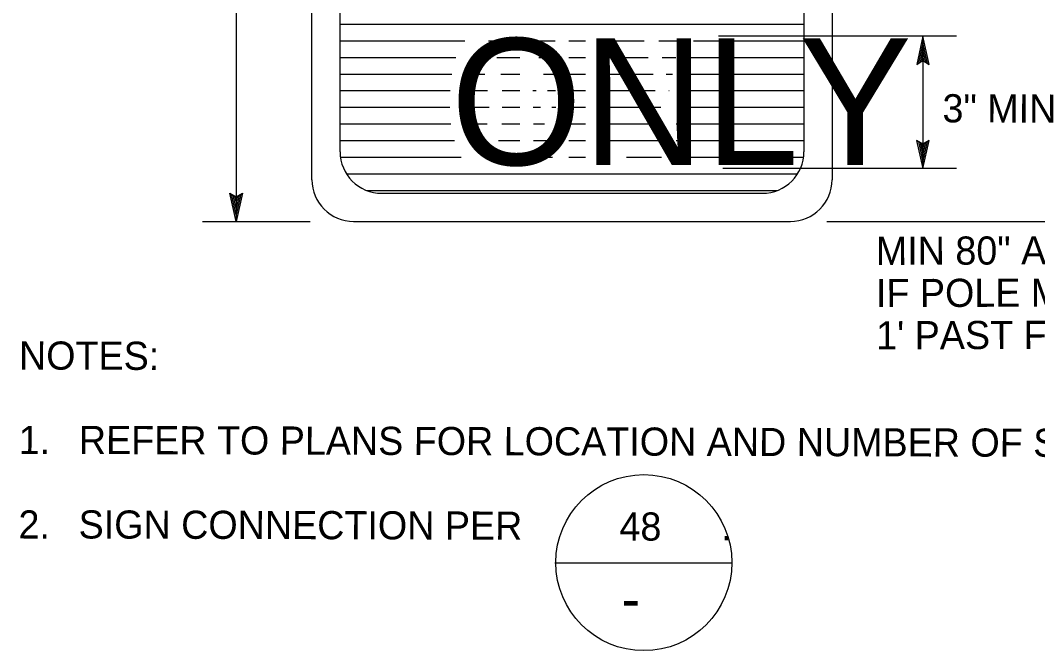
# Model space of a CAD drawing. Extents: x -121933 to -117742, y -103160 to -100084.
# Drawn here: x -118311.6 to -118094.9, y -101568.6 to -101434.3 of the extents above; entities that cross this region are included whole.
import ezdxf

# ---------------------------------------------------------------- set-up
doc = ezdxf.new("R2010")
doc.units = 0
for name, color, linetype in [('57 Undefined', 7, 'Continuous'), ('60 Nongeo Data', 7, 'Continuous'), ('Control (1)', 7, 'Continuous'), ('G-MARK', 7, 'Continuous'), ('G-TEXT', 7, 'Continuous'), ('Misc CnstDet(22)', 7, 'Continuous'), ('Sheet Format(10)', 7, 'Continuous')]:
    doc.layers.add(name, color=color, linetype=linetype)

msp = doc.modelspace()

# ---------------------------------------------------------------- linework, layer by layer
at = {"layer": '60 Nongeo Data'}
for p, q in [((-118249.47, -101468.31), (-118249.47, -101320.9)), ((-118138.69, -101320.93), (-118138.69, -101468.28)), ((-118243.48, -101462.3), (-118243.48, -101326.92)), ((-118144.67, -101326.92), (-118144.67, -101462.3)), ((-118243.48, -101435.11), (-118144.67, -101435.11)), ((-118243.48, -101438.66), (-118216.9, -101438.66)), ((-118211.87, -101438.66), (-118205.17, -101438.66)), ((-118202.1, -101438.66), (-118197.66, -101438.66)), ((-118194.78, -101438.66), (-118191.18, -101438.66)), ((-118187.97, -101438.66), (-118178.68, -101438.66)), ((-118175.58, -101438.66), (-118171.17, -101438.66)), ((-118168.18, -101438.66), (-118144.67, -101438.66)), ((-118243.48, -101442.2), (-118218.85, -101442.2)), ((-118214.99, -101442.2), (-118213.78, -101442.2)), ((-118210.12, -101442.2), (-118205.17, -101442.2)), ((-118201.15, -101442.2), (-118197.6, -101442.2)), ((-118194.78, -101442.2), (-118191.18, -101442.2)), ((-118187.97, -101442.2), (-118177.89, -101442.2)), ((-118174.85, -101442.2), (-118171.95, -101442.2)), ((-118169.01, -101442.2), (-118144.67, -101442.2)), ((-118243.48, -101445.75), (-118219.67, -101445.75)), ((-118216.75, -101445.75), (-118212.66, -101445.75)), ((-118209.26, -101445.75), (-118205.17, -101445.75)), ((-118200.13, -101445.75), (-118197.66, -101445.75)), ((-118194.78, -101445.75), (-118191.18, -101445.75)), ((-118187.97, -101445.75), (-118176.82, -101445.75)), ((-118174, -101445.75), (-118172.71, -101445.75)), ((-118169.9, -101445.75), (-118144.67, -101445.75)), ((-118243.48, -101449.3), (-118220.02, -101449.3)), ((-118217.14, -101449.3), (-118212.09, -101449.3)), ((-118208.98, -101449.3), (-118205.17, -101449.3)), ((-118202.44, -101449.3), (-118201.71, -101449.3)), ((-118199.28, -101449.3), (-118197.6, -101449.3)), ((-118194.78, -101449.3), (-118191.18, -101449.3)), ((-118187.97, -101449.3), (-118176.37, -101449.3)), ((-118173.44, -101449.3), (-118173.35, -101449.3)), ((-118170.74, -101449.3), (-118144.67, -101449.3)), ((-118243.48, -101452.84), (-118220.1, -101452.84)), ((-118217.18, -101452.84), (-118211.76, -101452.84)), ((-118208.95, -101452.84), (-118205.17, -101452.84)), ((-118202.33, -101452.84), (-118200.81, -101452.84)), ((-118198.35, -101452.84), (-118197.54, -101452.84)), ((-118194.78, -101452.84), (-118191.18, -101452.84)), ((-118187.97, -101452.84), (-118175.18, -101452.84)), ((-118171.69, -101452.84), (-118144.67, -101452.84)), ((-118243.48, -101456.39), (-118219.87, -101456.39)), ((-118216.79, -101456.39), (-118212.15, -101456.39)), ((-118209.03, -101456.39), (-118205.17, -101456.39)), ((-118202.27, -101456.39), (-118199.96, -101456.39)), ((-118197.51, -101456.39), (-118197.37, -101456.39)), ((-118194.78, -101456.39), (-118191.18, -101456.39)), ((-118187.97, -101456.39), (-118174.85, -101456.39)), ((-118171.86, -101456.39), (-118144.67, -101456.39)), ((-118243.48, -101459.94), (-118219.13, -101459.94)), ((-118215.5, -101459.94), (-118213.36, -101459.94)), ((-118209.77, -101459.94), (-118205.17, -101459.94)), ((-118202.27, -101459.94), (-118198.89, -101459.94)), ((-118194.78, -101459.94), (-118191.18, -101459.94)), ((-118187.97, -101459.94), (-118175.13, -101459.94)), ((-118171.86, -101459.94), (-118144.67, -101459.94)), ((-118243.4, -101463.49), (-118217.72, -101463.49)), ((-118211.21, -101463.49), (-118205.17, -101463.49)), ((-118202.22, -101463.49), (-118198.22, -101463.49)), ((-118194.78, -101463.49), (-118191.18, -101463.49)), ((-118182.45, -101463.49), (-118175.01, -101463.49)), ((-118171.86, -101463.49), (-118144.75, -101463.49)), ((-118242.11, -101467.03), (-118146.04, -101467.03)), ((-118237.78, -101470.58), (-118150.37, -101470.58)), ((-118234.61, -101471.16), (-118153.54, -101471.16)), ((-118245.63, -101475.59), (-118245.63, -101475.59)), ((-118244.6, -101476.2), (-118244.6, -101476.2)), ((-118240.63, -101477.15), (-118147.52, -101477.15))]:
    msp.add_line(p, q, dxfattribs=at)
for centre, start, end in [((-118234.61, -101462.3), 180, 270), ((-118153.54, -101462.3), 270, 0), ((-118240.6, -101468.28), 180, 270), ((-118147.56, -101468.28), 270, 0)]:
    msp.add_arc(centre, 8.87, start, end, dxfattribs=at)
at = {"layer": 'Control (1)'}
msp.add_line((-118197.73, -101549.92), (-118160.03, -101549.92), dxfattribs=at)
msp.add_circle((-118178.78, -101549.87), 18.75, dxfattribs=at)
at = {"layer": 'G-MARK'}
for p, q in [((-118265.63, -101312.06), (-118265.63, -101477.15)), ((-118119.33, -101437.7), (-118119.33, -101465.9))]:
    msp.add_line(p, q, dxfattribs=at)
at = {"layer": 'G-TEXT'}
for p, q in [((-118119.33, -101437.7), (-118120.66, -101443.7)), ((-118117.99, -101443.7), (-118119.33, -101437.7)), ((-118119.33, -101437.7), (-118119.33, -101437.7)), ((-118119.33, -101439.09), (-118120.3, -101443.47)), ((-118119.33, -101440.46), (-118119.95, -101443.29)), ((-118118.34, -101443.48), (-118119.33, -101439.08)), ((-118118.7, -101443.25), (-118119.33, -101440.46)), ((-118120.66, -101443.7), (-118119.33, -101442.9)), ((-118119.32, -101441.85), (-118119.59, -101443.05)), ((-118119.33, -101442.9), (-118117.99, -101443.7)), ((-118119.05, -101443.07), (-118119.32, -101441.85)), ((-118120.66, -101443.7), (-118120.66, -101443.7)), ((-118117.99, -101443.7), (-118117.99, -101443.7)), ((-118119.33, -101460.7), (-118120.67, -101459.9)), ((-118120.67, -101459.9), (-118120.67, -101459.9)), ((-118120.67, -101459.9), (-118119.33, -101465.9)), ((-118120.31, -101460.12), (-118119.33, -101464.52)), ((-118119.95, -101460.35), (-118119.33, -101463.14)), ((-118119.33, -101465.9), (-118118, -101459.9)), ((-118118, -101459.9), (-118119.33, -101460.7)), ((-118119.33, -101463.14), (-118118.7, -101460.32)), ((-118119.32, -101464.51), (-118118.36, -101460.14)), ((-118118, -101459.9), (-118118, -101459.9)), ((-118119.61, -101460.53), (-118119.33, -101461.76)), ((-118119.33, -101461.76), (-118119.06, -101460.55)), ((-118119.33, -101465.9), (-118119.33, -101465.9)), ((-118265.63, -101477.15), (-118266.96, -101471.15)), ((-118266.96, -101471.15), (-118266.96, -101471.15)), ((-118266.96, -101471.15), (-118265.63, -101471.95)), ((-118265.63, -101471.95), (-118264.29, -101471.15)), ((-118264.29, -101471.15), (-118265.63, -101477.15)), ((-118264.29, -101471.15), (-118264.29, -101471.15)), ((-118265.63, -101475.76), (-118266.6, -101471.39)), ((-118265.63, -101474.39), (-118266.26, -101471.56)), ((-118265.63, -101473.01), (-118265.9, -101471.8)), ((-118264.65, -101471.37), (-118265.63, -101475.77)), ((-118265.01, -101471.6), (-118265.63, -101474.39)), ((-118265.35, -101471.78), (-118265.63, -101473.01)), ((-118265.63, -101477.15), (-118265.63, -101477.15))]:
    msp.add_line(p, q, dxfattribs=at)
at = {"layer": 'Misc CnstDet(22)'}
for p, q in [((-118112.2, -101437.7), (-118162.9, -101437.7)), ((-118112.2, -101465.9), (-118161.97, -101465.9)), ((-118272.76, -101477.15), (-118249.87, -101477.15)), ((-118139.78, -101477.15), (-117979.57, -101477.15))]:
    msp.add_line(p, q, dxfattribs=at)

# ---------------------------------------------------------------- texts
at = {"layer": '57 Undefined'}
for s, rotation, p in [('3" MIN', 359.832, (-118115.17, -101456.05)), ('MIN 80" ABOVE FINISHED GRADE', 0.168, (-118129.35, -101486.43)), ('IF POLE MOUNTED. LOCATE POLE', 0.168, (-118129.33, -101495.43)), ("1' PAST FRONT OF PARKING SPACE.", 0.168, (-118129.3, -101504.43)), ('NOTES:  ', 359.832, (-118311.88, -101508.72)), ('1.', 359.832, (-118311.94, -101526.72)), ('REFER TO PLANS FOR LOCATION AND NUMBER OF SIGNS REQUIRED.', 359.832, (-118299.13, -101526.72)), ('2.', 359.832, (-118311.99, -101544.72)), ('SIGN CONNECTION PER                   .', 359.832, (-118299.18, -101544.72))]:
    msp.add_text(s, height=6, rotation=rotation, dxfattribs=at).set_placement(p)
at = {"layer": '60 Nongeo Data'}
msp.add_text('ONLY', height=26.983, dxfattribs=at).set_placement((-118219.95, -101465.14))
at = {"layer": 'Control (1)'}
msp.add_text('-', height=8.75, dxfattribs=at).set_placement((-118183.49, -101561.92))
at = {"layer": 'Sheet Format(10)'}
msp.add_text('48', height=6, dxfattribs=at).set_placement((-118183.97, -101545.17))

doc.saveas('drawing.dxf')
